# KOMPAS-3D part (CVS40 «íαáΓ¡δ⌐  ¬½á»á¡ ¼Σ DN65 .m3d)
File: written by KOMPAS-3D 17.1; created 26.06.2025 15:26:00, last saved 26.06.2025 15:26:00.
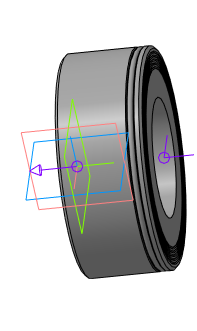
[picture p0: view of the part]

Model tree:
1. Эскиз:1
2. Элемент вращения:1
     Угол 1 = 360
3. Присоединительная точка:1
4. Присоединительная точка:2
